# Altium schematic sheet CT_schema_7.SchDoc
size 274 x 160 mm
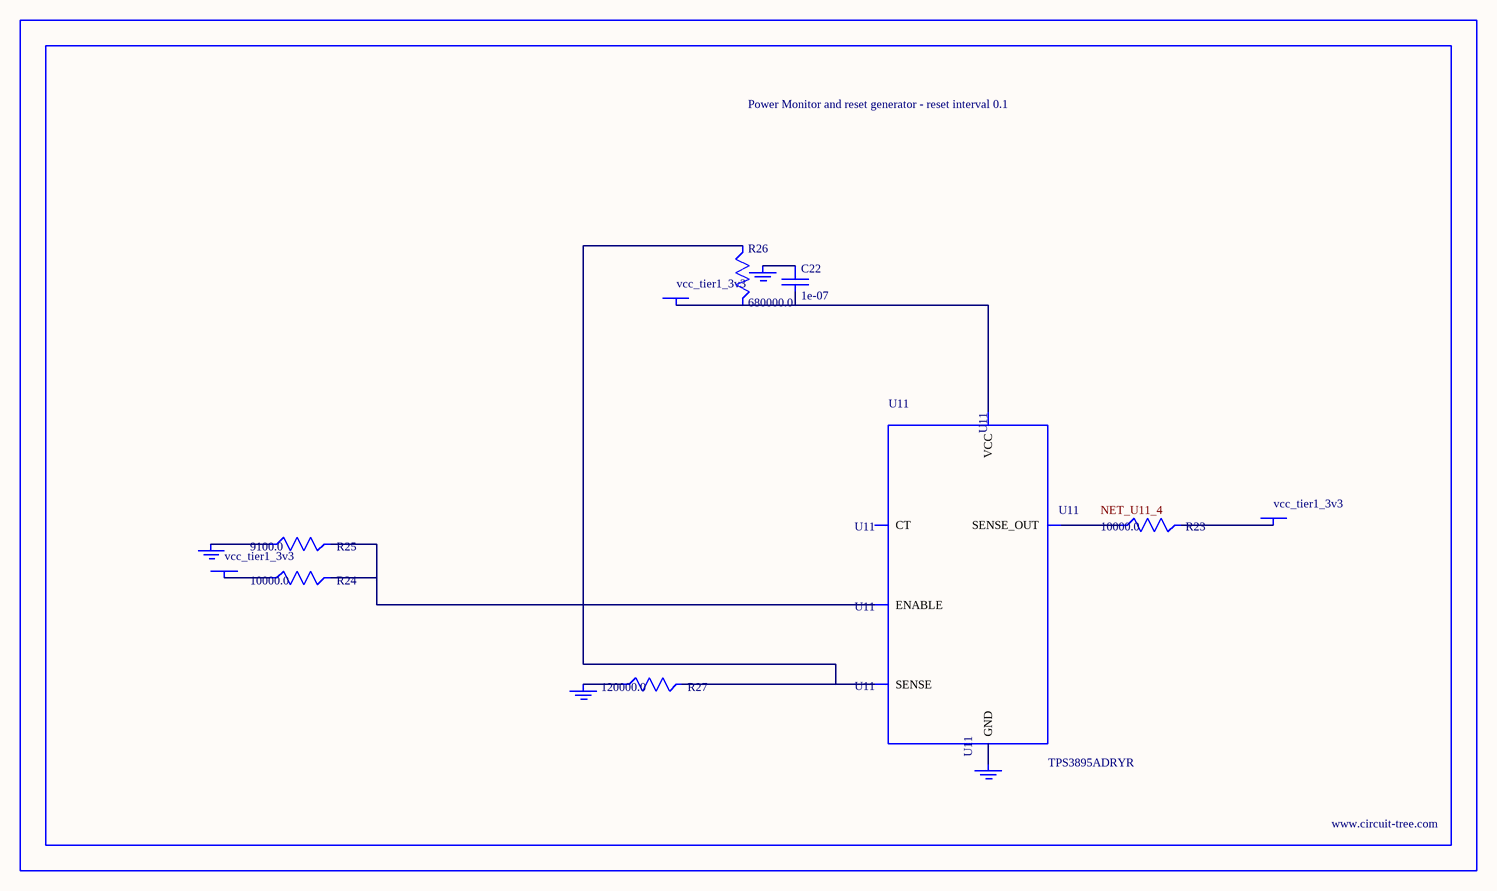
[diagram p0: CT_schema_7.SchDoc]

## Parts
BORDER6  (no value)
C22  1e-07  [C0402]
GND_INSTANCE_6_0  (no value)
GND_INSTANCE_6_1  (no value)
GND_INSTANCE_6_2  (no value)
GND_INSTANCE_6_3  (no value)
POWER_INSTANCE_6_0  vcc_tier1_3v3
POWER_INSTANCE_6_1  vcc_tier1_3v3
POWER_INSTANCE_6_2  vcc_tier1_3v3
R23  10000.0  [R0603]
R24  10000.0  [R0603]
R25  9100.0  [R0603]
R26  680000.0  [R0603]
R27  120000.0  [R0603]
U11  TPS3895ADRYR  [SON-6]

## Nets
NetC22_1: C22.1 GND_INSTANCE_6_2.0(GND)
NetC22_2: C22.2 POWER_INSTANCE_6_2.0(PWR) R26.2 U11.6(VCC)
NetGND_INSTANCE_6_0_0: GND_INSTANCE_6_0.0(GND) R25.1
NetGND_INSTANCE_6_1_0: GND_INSTANCE_6_1.0(GND) R27.1
NetGND_INSTANCE_6_3_0: GND_INSTANCE_6_3.0(GND) U11.2(GND)
NetPOWER_INSTANCE_6_0_0: POWER_INSTANCE_6_0.0(PWR) R24.1
NetPOWER_INSTANCE_6_1_0: POWER_INSTANCE_6_1.0(PWR) R23.2
NetR23_1: R23.1 U11.4(SENSE_OUT)
NetR24_2: R24.2 R25.2 U11.1(ENABLE)
NetR26_1: R26.1 R27.2 U11.3(SENSE)

Not connected (* = marked no-connect by the designer): U11 5(CT)

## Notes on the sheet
- Labels drawn without touching a wire or pin: NET_U11_4

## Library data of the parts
BORDER6 = BORDER_PAGE6
C22 = C0402C104K3RACTU
GND_INSTANCE_6_0-GND_INSTANCE_6_3 = GND
POWER_INSTANCE_6_0-POWER_INSTANCE_6_2 = PWR
R23 R24 = RC0603JR-0710KL
R25 = RC0603JR-079K1L
R26 = RC0603JR-07680KL
R27 = RC0603JR-07120KL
